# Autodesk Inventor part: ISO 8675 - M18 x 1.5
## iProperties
Author: Philippe
Created: 2001-12
Part Number: ISO 8675 - M18 x 1.5
Material: Par défaut
Catalog Web Link: file:///C:/Program Files/Autodesk/Inventor 5/Content/Iso/index.htm?doNavigateId=196B3CA3-BC05-4714-90BC-8FFFE16B681C|6ACDD1BAAAF44508AF8486658C754D94|true
Description: Ecrou hexagonal
Document SubType Name: Standard Catalog Part
Standard: ISO 8675 - M18 x 1.5
Designer: Philippe
CLASSIFICATION: 31161727 un/spsc
MANUFACTURER: ISO Système de normes
Control State: 0
Master: False
Checked Out: False
PropertySet Name: Design Tracking Control
Shininess: 20.0
Angle Display Precision: 2
Document Length Units: 11269
Document Angle Units: 11283
Document Time Units: 11279
Document Mass Units: 11290
Document Length Units Precision: 3
Document Angle Units Precision: 2
Compacted: False
PropertySet Name: _Private Model Information
Density: 0.0
Volumn: 0.0
Area: 0.0
PropertySet Name: Model Information
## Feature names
1. Base1
